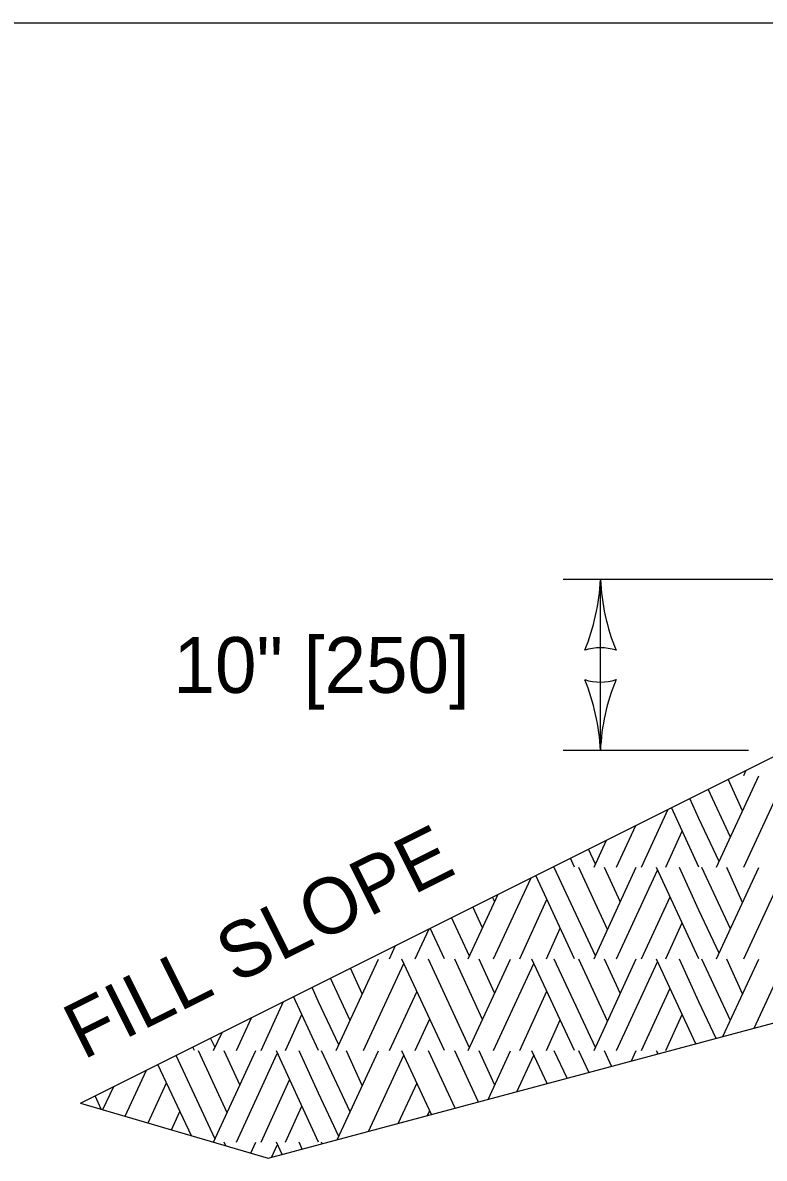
# Model space of a CAD drawing. Extents: x 49991.4 to 50021, y 49987.6 to 50011.4.
# Drawn here: x 50010.982 to 50011.779, y 49989.342 to 49990.562 of the extents above; entities that cross this region are included whole.
import ezdxf

# ---------------------------------------------------------------- set-up
doc = ezdxf.new("R2010")
doc.units = 0
for name, color, linetype in [('Level 1', 7, 'Continuous'), ('Level 2', 7, 'Continuous'), ('Level 3', 7, 'Continuous')]:
    doc.layers.add(name, color=color, linetype=linetype)

msp = doc.modelspace()

# ---------------------------------------------------------------- linework, layer by layer
at = {"layer": 'Level 1'}
for p, q in [((49999.3835, 49990.5622), (50016.7501, 49990.5622)), ((50011.728, 49989.6548), (50011.7735, 49989.753)), ((50011.7573, 49989.7533), (50011.76, 49989.759)), ((50011.743, 49989.6871), (50011.719, 49989.7385)), ((50011.7561, 49989.7155), (50011.7407, 49989.7493)), ((50011.7573, 49989.6548), (50011.8009, 49989.7484)), ((50011.7091, 49989.7072), (50011.6993, 49989.7286)), ((50011.6476, 49989.6548), (50011.676, 49989.717)), ((50011.7091, 49989.6548), (50011.6795, 49989.7188)), ((50011.7308, 49989.6609), (50011.7091, 49989.7072)), ((50011.6207, 49989.6548), (50011.6415, 49989.6997)), ((50011.6735, 49989.6548), (50011.6912, 49989.6935)), ((50011.5964, 49989.6548), (50011.6098, 49989.6839)), ((50011.5756, 49989.6548), (50011.5711, 49989.6645)), ((50011.5979, 49989.6579), (50011.5903, 49989.6741)), ((50011.5979, 49989.5594), (50011.5537, 49989.6545)), ((50011.611, 49989.5878), (50011.5802, 49989.6545)), ((50011.5964, 49989.5564), (50011.6418, 49989.6548)), ((50011.6247, 49989.6173), (50011.6076, 49989.6545)), ((50011.7091, 49989.5564), (50011.6637, 49989.6545)), ((50011.7091, 49989.6088), (50011.6881, 49989.6545)), ((50011.743, 49989.5887), (50011.7122, 49989.6545)), ((50011.728, 49989.5564), (50011.7735, 49989.6545)), ((50011.7561, 49989.617), (50011.739, 49989.6545)), ((50011.4885, 49989.5564), (50011.5289, 49989.6434)), ((50011.5756, 49989.5564), (50011.5337, 49989.6458)), ((50011.6207, 49989.5564), (50011.6646, 49989.6515)), ((50011.7573, 49989.5564), (50011.8009, 49989.6499)), ((50011.4613, 49989.5564), (50011.4934, 49989.6257)), ((50011.4894, 49989.6182), (50011.4874, 49989.6227)), ((50011.5165, 49989.5564), (50011.5458, 49989.6201)), ((50011.6476, 49989.5564), (50011.6781, 49989.6231)), ((50011.4766, 49989.5896), (50011.4662, 49989.6121)), ((50011.7308, 49989.5625), (50011.7091, 49989.6088)), ((50011.4626, 49989.5591), (50011.4433, 49989.6006)), ((50011.6735, 49989.5564), (50011.6912, 49989.5951)), ((50011.4043, 49989.5564), (50011.4191, 49989.5886)), ((50011.4357, 49989.5564), (50011.4204, 49989.5892)), ((50011.5452, 49989.5564), (50011.5601, 49989.5893)), ((50011.3766, 49989.5564), (50011.3832, 49989.5706)), ((50011.3193, 49989.4579), (50011.3647, 49989.5561)), ((50011.4357, 49989.4579), (50011.39, 49989.5561)), ((50011.4626, 49989.4607), (50011.4184, 49989.5561)), ((50011.4766, 49989.4911), (50011.4467, 49989.5561)), ((50011.4613, 49989.4579), (50011.5068, 49989.5561)), ((50011.4894, 49989.5198), (50011.4729, 49989.5561)), ((50011.5756, 49989.4579), (50011.5296, 49989.5561)), ((50011.5979, 49989.461), (50011.5537, 49989.5561)), ((50011.611, 49989.4893), (50011.5802, 49989.5561)), ((50011.5964, 49989.4579), (50011.6418, 49989.5564)), ((50011.6247, 49989.5189), (50011.6076, 49989.5561)), ((50011.7058, 49989.4651), (50011.6637, 49989.5561)), ((50011.7091, 49989.5103), (50011.6881, 49989.5561)), ((50011.743, 49989.4902), (50011.7122, 49989.5561)), ((50011.735, 49989.4729), (50011.7735, 49989.5561)), ((50011.7561, 49989.5186), (50011.739, 49989.5561)), ((50011.3473, 49989.5186), (50011.3347, 49989.5463)), ((50011.3486, 49989.4579), (50011.3921, 49989.5515)), ((50011.4885, 49989.4579), (50011.5317, 49989.5512)), ((50011.6207, 49989.4579), (50011.6646, 49989.553)), ((50011.7685, 49989.4819), (50011.8009, 49989.5515)), ((50011.3342, 49989.4902), (50011.3131, 49989.5355)), ((50011.3004, 49989.5103), (50011.2934, 49989.5257)), ((50011.3766, 49989.4579), (50011.4062, 49989.5216)), ((50011.5165, 49989.4579), (50011.5458, 49989.5216)), ((50011.6476, 49989.4579), (50011.6781, 49989.5247)), ((50011.2388, 49989.4579), (50011.2628, 49989.5104)), ((50011.3004, 49989.4579), (50011.2736, 49989.5158)), ((50011.322, 49989.464), (50011.3004, 49989.5103)), ((50011.7275, 49989.4709), (50011.7091, 49989.5103)), ((50011.2647, 49989.4579), (50011.2824, 49989.4966)), ((50011.6735, 49989.4579), (50011.6912, 49989.4966)), ((50011.212, 49989.4579), (50011.2283, 49989.4931)), ((50011.2463, 49989.342), (50011.7993, 49989.4902)), ((50011.4043, 49989.4579), (50011.4199, 49989.4917)), ((50011.5452, 49989.4579), (50011.5601, 49989.4908)), ((50011.1892, 49989.461), (50011.1844, 49989.4712)), ((50011.1876, 49989.4579), (50011.1966, 49989.4773)), ((50011.1669, 49989.4579), (50011.1652, 49989.4616)), ((50011.2023, 49989.3909), (50011.1715, 49989.4576)), ((50011.1876, 49989.3595), (50011.233, 49989.4579)), ((50011.216, 49989.4204), (50011.1989, 49989.4576)), ((50011.3004, 49989.3595), (50011.255, 49989.4576)), ((50011.3004, 49989.4119), (50011.2794, 49989.4576)), ((50011.3342, 49989.3918), (50011.3035, 49989.4576)), ((50011.3204, 49989.3619), (50011.3647, 49989.4576)), ((50011.3473, 49989.4201), (50011.3303, 49989.4576)), ((50011.4219, 49989.3891), (50011.39, 49989.4576)), ((50011.447, 49989.3958), (50011.4184, 49989.4576)), ((50011.4721, 49989.4025), (50011.4467, 49989.4576)), ((50011.4894, 49989.4213), (50011.4729, 49989.4576)), ((50011.4826, 49989.4053), (50011.5068, 49989.4576)), ((50011.5461, 49989.4224), (50011.5296, 49989.4576)), ((50011.5674, 49989.4281), (50011.5537, 49989.4576)), ((50011.5909, 49989.4344), (50011.5802, 49989.4576)), ((50011.6153, 49989.4409), (50011.6076, 49989.4576)), ((50011.6366, 49989.4466), (50011.6418, 49989.4579)), ((50011.6653, 49989.4543), (50011.6637, 49989.4576)), ((50011.1892, 49989.3625), (50011.1473, 49989.4526)), ((50011.212, 49989.3595), (50011.2559, 49989.4546)), ((50011.3539, 49989.3709), (50011.3921, 49989.453)), ((50011.5136, 49989.4136), (50011.5317, 49989.4527)), ((50011.6644, 49989.454), (50011.6646, 49989.4546)), ((50011.0926, 49989.3872), (50011.1156, 49989.4368)), ((50011.1637, 49989.3663), (50011.1278, 49989.4429)), ((50011.1172, 49989.38), (50011.137, 49989.4232)), ((50011.2388, 49989.3595), (50011.2693, 49989.4262)), ((50011.3859, 49989.3794), (50011.4062, 49989.4232)), ((50011.5453, 49989.4221), (50011.5458, 49989.4232)), ((50011.0669, 49989.3948), (50011.0603, 49989.4091)), ((50011.0687, 49989.3943), (50011.0802, 49989.4191)), ((50011.322, 49989.3656), (50011.3004, 49989.4119)), ((50011.0447, 49989.4013), (50011.2463, 49989.342)), ((50011.2647, 49989.3595), (50011.2824, 49989.3982)), ((50011.1424, 49989.3726), (50011.1514, 49989.3924)), ((50011.4174, 49989.3879), (50011.4199, 49989.3933)), ((50011.2275, 49989.3475), (50011.233, 49989.3595)), ((50011.2006, 49989.3555), (50011.1989, 49989.3592)), ((50011.2498, 49989.343), (50011.2559, 49989.3561)), ((50011.2611, 49989.346), (50011.255, 49989.3592)), ((50011.2828, 49989.3518), (50011.2794, 49989.3592)), ((50011.3042, 49989.3576), (50011.3035, 49989.3592))]:
    msp.add_line(p, q, dxfattribs=at)
msp.add_lwpolyline([(50011.0447, 49989.4013), (50011.8025, 49989.7802), (50011.9613, 49989.891), (50012.0991, 49989.964), (50012.2318, 49989.9732), (50012.3828, 49989.9091), (50012.4676, 49989.8447), (50012.5525, 49989.7802), (50012.643, 49989.7177), (50013.2924, 49989.7454), (50013.5638, 49989.7802), (50014.0674, 49989.7802)], dxfattribs=at)
at = {"layer": 'Level 3'}
for p, q in [((50012.0591, 49989.964), (50011.5633, 49989.964)), ((50011.6033, 49989.7802), (50011.6033, 49989.964)), ((50011.7625, 49989.7802), (50011.5633, 49989.7802))]:
    msp.add_line(p, q, dxfattribs=at)
for centre, radius, start, end in [((50011.3811, 49989.9732), 0.2223, 337.456, 357.6395), ((50011.836, 49989.9755), 0.233, 182.8273, 202.0772), ((50011.6033, 49989.8358), 0.0548, 72.1388, 107.8612), ((50011.6033, 49989.9085), 0.0548, 252.1388, 287.8612), ((50011.3706, 49989.7687), 0.233, 2.8273, 22.0772), ((50011.8254, 49989.7711), 0.2223, 157.456, 177.6395)]:
    msp.add_arc(centre, radius, start, end, dxfattribs=at)

# ---------------------------------------------------------------- texts
at = {"layer": 'Level 2'}
msp.add_text('10" [250]', height=0.06, dxfattribs=at).set_placement((50011.1444, 49989.8421))
msp.add_text('FILL SLOPE', height=0.06, rotation=26.5651, dxfattribs=at).set_placement((50011.0473, 49989.4473))

doc.saveas('drawing.dxf')
